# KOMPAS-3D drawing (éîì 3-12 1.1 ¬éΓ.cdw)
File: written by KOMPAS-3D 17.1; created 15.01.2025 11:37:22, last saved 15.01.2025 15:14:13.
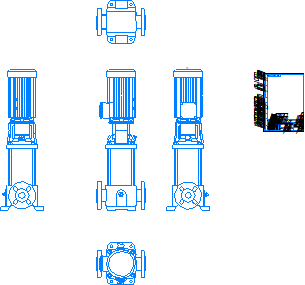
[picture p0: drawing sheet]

Sheet 1: A4, portrait

Title block, sheet 1: name: ВМН 3-12 1.1 кВт; designation: ВМН 3-12 1.1 кВт; material: Сталь 10  ГОСТ 1050-2013; mass: 68,16; sheets: 1; sheet format: A4; stored path: \\adlc.lan\data\АДЛ_ПКД\3D-модели\ADL production\Насосы ГРАНПАМП\Насосы ВМН\ВМН3\KOMPAS 3D\ВМН 3-12 1.1 кВт.cdw

Views: Вид 1, Спереди, Проекционный вид 2, Проекционный вид 3, Проекционный вид 4, Проекционный вид 5
Referenced files in \\adlc.lan\data\АДЛ_ПКД\3D-модели\ADL production\Насосы ГРАНПАМП\Насосы ВМН\ВМН3\KOMPAS 3D\: ВМН 3-12 1.1 кВт.m3d
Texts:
  Andrey
  АДЛ
Dimensions and other numbers on the sheet: 1:1; 1; 68,16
